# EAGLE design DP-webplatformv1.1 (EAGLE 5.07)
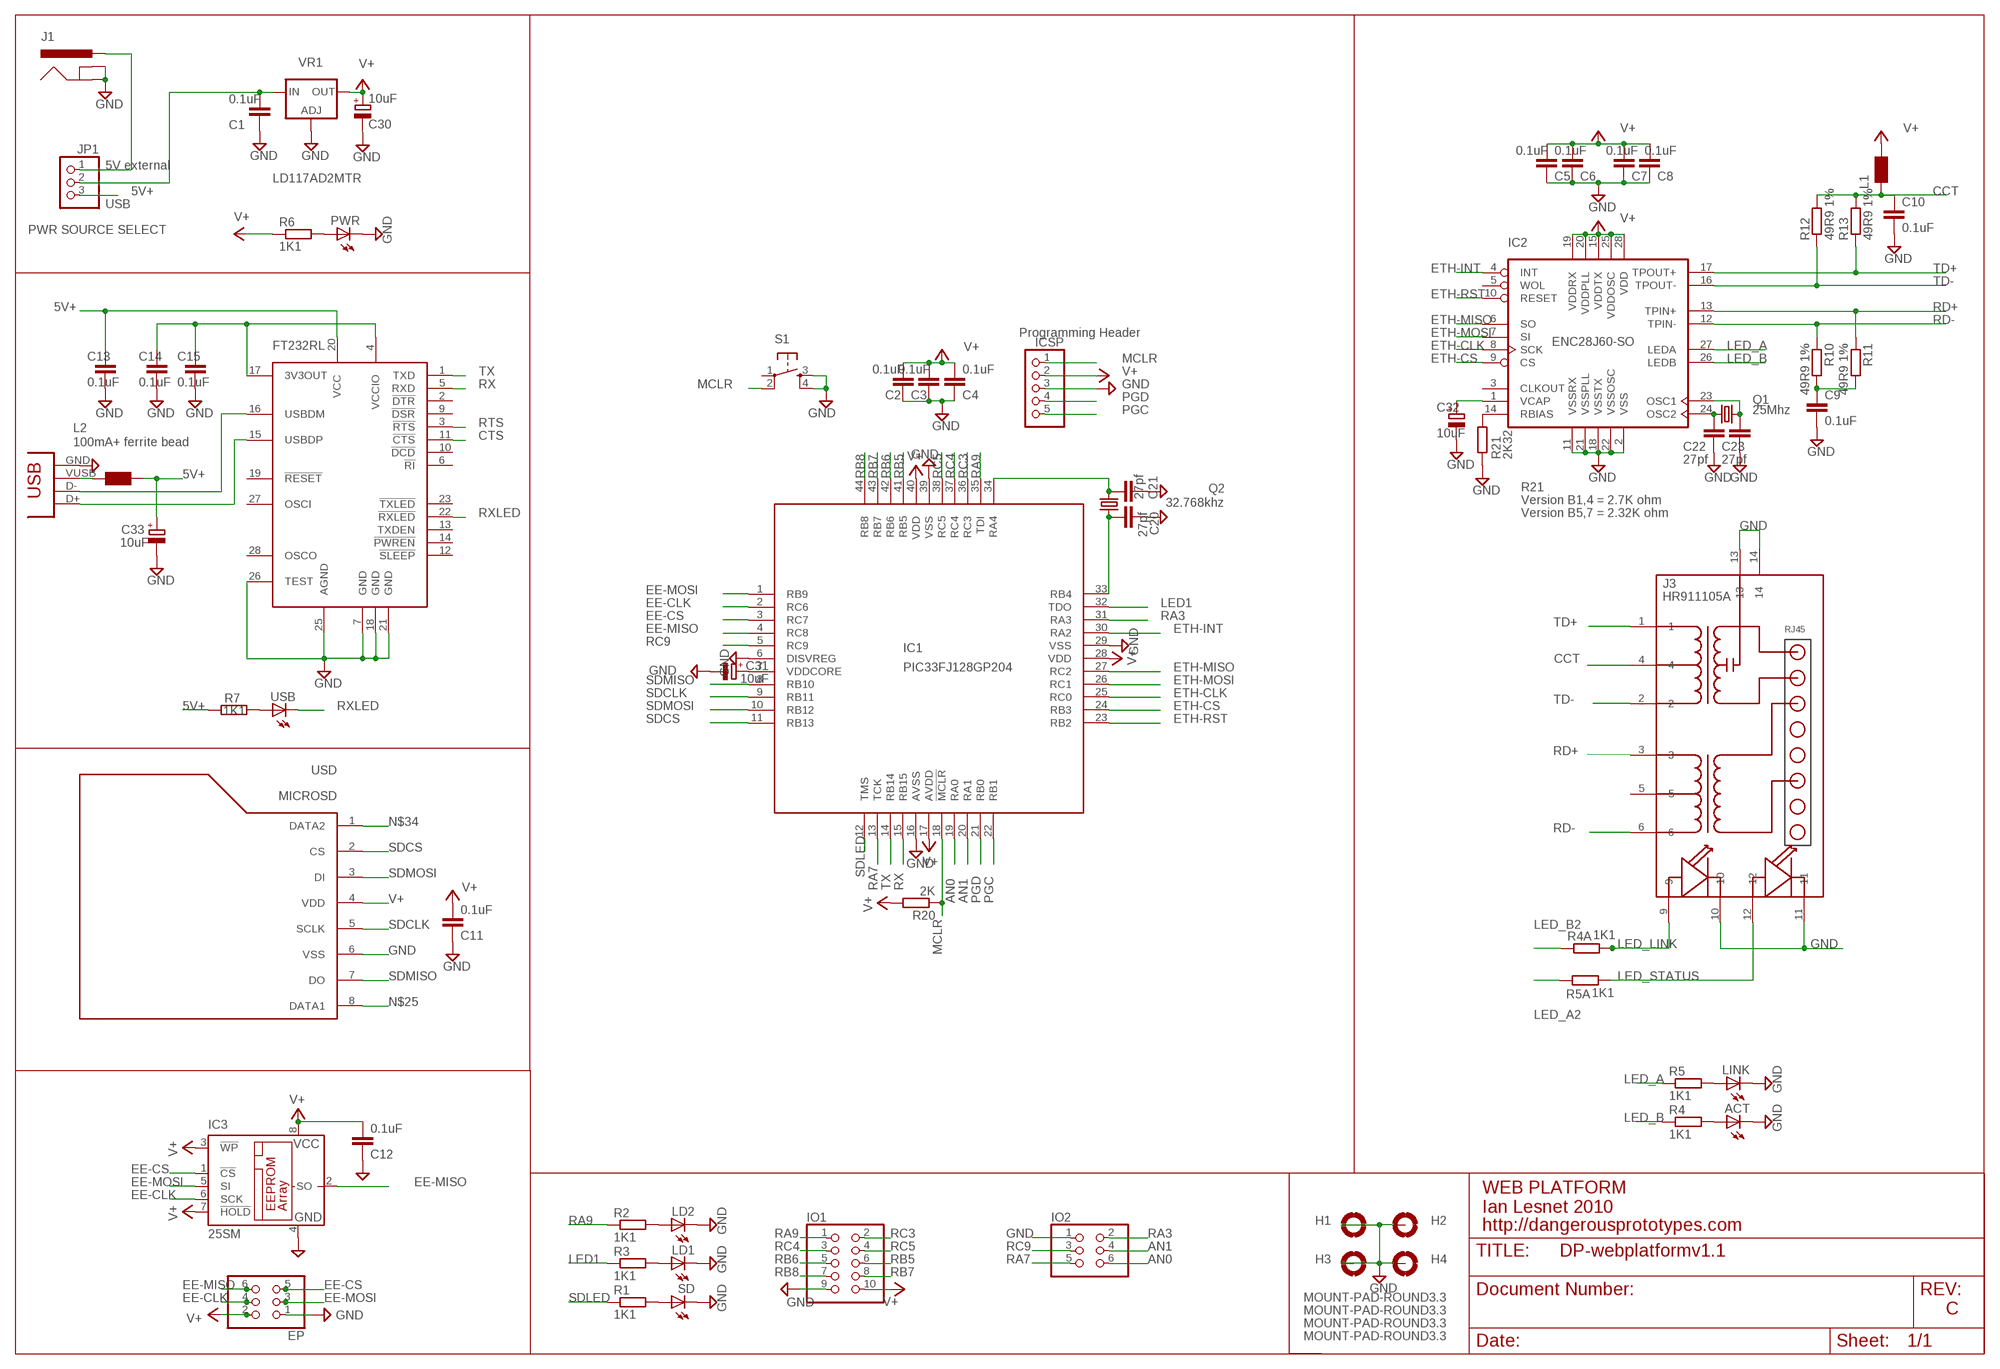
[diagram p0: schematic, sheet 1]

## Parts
ACT  LEDCHIPLED_0805  [CHIPLED_0805]
C1  0.1uF  C-EUC0805  [C0805]
C2  0.1uF  C-EUC0805  [C0805]
C3  0.1uF  C-EUC0805  [C0805]
C4  0.1uF  C-EUC0805  [C0805]
C5  0.1uF  C-EUC0805  [C0805]
C6  0.1uF  C-EUC0805  [C0805]
C7  0.1uF  C-EUC0805  [C0805]
C8  0.1uF  C-EUC0805  [C0805]
C9  0.1uF  C-EUC0805  [C0805]
C10  0.1uF  C-EUC0805  [C0805]
C11  0.1uF  C-EUC0805  [C0805]
C12  0.1uF  C-EUC0805  [C0805]
C13  0.1uF  C-EUC0805  [C0805]
C14  0.1uF  C-EUC0805  [C0805]
C15  0.1uF  C-EUC0805  [C0805]
C20  27pf  C-EUC0805  [C0805]
C21  27pf  C-EUC0805  [C0805]
C22  27pf  C-EUC0805  [C0805]
C23  27pf  C-EUC0805  [C0805]
C30  10uF  CPOL-EUSMCA  [SMC_A]
C31  10uF  CPOL-EUSMCA  [SMC_A]
C32  10uF  CPOL-EUSMCA  [SMC_A]
C33  10uF  CPOL-EUSMCA  [SMC_A]
CONN1  CONN_USB  [CONN_USB_MINI-B]
EP  PINHD-2X3  [2X03]
H1  MOUNT-PAD-ROUND3.3  [3,3-PAD]
H2  MOUNT-PAD-ROUND3.3  [3,3-PAD]
H3  MOUNT-PAD-ROUND3.3  [3,3-PAD]
H4  MOUNT-PAD-ROUND3.3  [3,3-PAD]
IC1  PIC33FJ128GP204  PIC24FJ64GA004  [TQFP44]
IC2  ENC28J60-SO  [SO28W]
IC3  25SM  [SO-08M]
IC4  FT232RL  [SSOP28]
ICSP  PINHD-1X05_2.54-S  [1X05-S]
IO1  PINHD-2X5  [2X05]
IO2  PINHD-2X3  [2X03]
J1  POWER_JACKSMD  [POWER_JACK_SMD]
J3  HR911105A  [HR911105A]
JP1  PINHD-1X03_2.54-S  [1X03-S]
L1  WE-KIL_0805  [WE-KI_0805_B]
L2  100mA+ ferrite bead  WE-KIL_0805  [WE-KI_0805_B]
LD1  LEDCHIPLED_0805  [CHIPLED_0805]
LD2  LEDCHIPLED_0805  [CHIPLED_0805]
LINK  LEDCHIPLED_0805  [CHIPLED_0805]
PWR  LEDCHIPLED_0805  [CHIPLED_0805]
Q1  25Mhz  CRYSTALHC49UP  [HC49UP]
Q2  32.768khz  CRYSTALMM20SS  [MM20SS]
R1  1K1  R-EU_R0805  [R0805]
R2  1K1  R-EU_R0805  [R0805]
R3  1K1  R-EU_R0805  [R0805]
R4  1K1  R-EU_R0805  [R0805]
R4A  1K1  R-EU_R0805  [R0805]
R5  1K1  R-EU_R0805  [R0805]
R5A  1K1  R-EU_R0805  [R0805]
R6  1K1  R-EU_R0805  [R0805]
R7  1K1  R-EU_M0805  [M0805]
R10  49R9 1%  R-EU_R0805  [R0805]
R11  49R9 1%  R-EU_R0805  [R0805]
R12  49R9 1%  R-EU_R0805  [R0805]
R13  49R9 1%  R-EU_R0805  [R0805]
R20  2K  R-EU_R0805  [R0805]
R21  2K32  R-EU_R0805  [R0805]
S1  SMD_TACT_SMALL  [TACT_SWITCH_SMALL]
SD  LEDCHIPLED_0805  [CHIPLED_0805]
USB  LEDCHIP-LED0805  [CHIP-LED0805]
USD  MICROSD  [MICROSD]
VR1  LD117AD2MTR  [D2PACK]

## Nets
5V+: C13.1 C33.+ IC4.20(VCC) JP1.3 L2.1 R7.2
AN0: IC1.19(RA0) IO2.6
AN1: IC1.20(RA1) IO2.4
BUS_PWR: CONN1.VUSB L2.2
CCT: C10.1 J3.4 L1.2 R12.2 R13.2
CTS: IC4.11(!CTS)
EE-CLK: EP.4 IC1.2(RC6) IC3.6(SCK)
EE-CS: EP.5 IC1.3(RC7) IC3.1(!CS)
EE-MISO: EP.6 IC1.4(RC8) IC3.2(SO)
EE-MOSI: EP.3 IC1.1(RB9) IC3.5(SI)
ETH-CLK: IC1.25(RC0) IC2.8(SCK)
ETH-CS: IC1.24(RB3) IC2.9(CS)
ETH-INT: IC1.30(RA2) IC2.4(INT)
ETH-MISO: IC1.27(RC2) IC2.6(SO)
ETH-MOSI: IC1.26(RC1) IC2.7(SI)
ETH-RST: IC1.23(RB2) IC2.10(RESET)
GND: ACT.C C1.2 C2.2 C3.2 C4.2 C5.2 C6.2 C7.2 C8.2 C9.2 C10.2 C11.2 C12.2 C13.2 C14.2 C15.2 C20.2 C21.2 C22.2 C23.2 C30.- C31.- C32.- C33.- CONN1.GND EP.1 H1.B3,3(MOUNT) H2.B3,3(MOUNT) H3.B3,3(MOUNT) H4.B3,3(MOUNT) IC1.6(DISVREG) IC1.16(AVSS) IC1.29(VSS) IC1.39(VSS) IC2.2(VSS) IC2.11(VSSRX) IC2.18(VSSTX) IC2.21(VSSPLL) IC2.22(VSSOSC) IC3.4(GND) IC4.7(GND) IC4.18(GND) IC4.21(GND) IC4.25(AGND) IC4.26(TEST) ICSP.3 IO1.9 IO2.1 J1.GND(GNDBREAK) J1.P$4(GND) J3.10 J3.11 J3.13 J3.14 LD1.C LD2.C LINK.C PWR.C R21.1 S1.3 S1.4 SD.C USD.6(VSS) VR1.1(ADJ)
LED1: IC1.32(TDO) R3.1
LED_A: IC2.27(LEDA) R5.1
LED_A2: R5A.1
LED_B: IC2.26(LEDB) R4.1
LED_B2: R4A.1
LED_LINK: J3.9 R4A.2
LED_STATUS: J3.12 R5A.2
MCLR: IC1.18(!MCLR) ICSP.1 R20.1 S1.2
N$5: C20.1 IC1.33(RB4) Q2.1
N$6: C32.+ IC2.1(VCAP)
N$7: IC2.14(RBIAS) R21.2
N$9: C22.1 IC2.24(OSC2) Q1.1
N$10: R7.1 USB.A
N$11: R1.2 SD.A
N$12: C23.1 IC2.23(OSC1) Q1.2
N$13: LD2.A R2.2
N$14: LINK.A R5.2
N$15: CONN1.D+ IC4.15(USBDP)
N$16: CONN1.D- IC4.16(USBDM)
N$17: C14.1 C15.1 IC4.4(VCCIO) IC4.17(3V3OUT)
N$18: C31.+ IC1.7(VDDCORE)
N$19: C21.1 IC1.34(RA4) Q2.4
N$20: ACT.A R4.2
N$22: C9.1 R10.2 R11.2
N$25: USD.8(DATA1)
N$28: LD1.A R3.2
N$29: PWR.A R6.2
N$34: USD.1(DATA2)
PGC: IC1.22(RB1) ICSP.5
PGD: IC1.21(RB0) ICSP.4
RA3: IC1.31(RA3) IO2.2
RA7: IC1.13(TCK) IO2.5
RA9: IC1.35(TDI) IO1.1 R2.1
RB5: IC1.41(RB5) IO1.6
RB6: IC1.42(RB6) IO1.5
RB7: IC1.43(RB7) IO1.8
RB8: IC1.44(RB8) IO1.7
RC3: IC1.36(RC3) IO1.2
RC4: IC1.37(RC4) IO1.3
RC5: IC1.38(RC5) IO1.4
RC9: IC1.5(RC9) IO2.3
RD+: IC2.13(TPIN+) J3.3 R11.1
RD-: IC2.12(TPIN-) J3.6 R10.1
RTS: IC4.3(!RTS)
RX: IC1.15(RB15) IC4.5(RXD)
RXLED: IC4.22(!RXLED) USB.C
SDCLK: IC1.9(RB11) USD.5(SCLK)
SDCS: IC1.11(RB13) USD.2(CS)
SDLED: IC1.12(TMS) R1.1
SDMISO: IC1.8(RB10) USD.7(DO)
SDMOSI: IC1.10(RB12) USD.3(DI)
TD+: IC2.17(TPOUT+) J3.1 R13.1
TD-: IC2.16(TPOUT-) J3.2 R12.1
TX: IC1.14(RB14) IC4.1(TXD)
V+: C2.1 C3.1 C4.1 C5.1 C6.1 C7.1 C8.1 C11.1 C12.1 C30.+ EP.2 IC1.17(AVDD) IC1.28(VDD) IC1.40(VDD) IC2.15(VDDTX) IC2.19(VDDRX) IC2.20(VDDPLL) IC2.25(VDDOSC) IC2.28(VDD) IC3.3(!WP) IC3.7(!HOLD) IC3.8(VCC) ICSP.2 IO1.10 L1.1 R6.1 R20.2 USD.4(VDD) VR1.2(OUT)
VBAT: C1.1 JP1.2 VR1.3(IN)
VEXT: J1.VIN0(PWR) JP1.1
Unconnected: IC2.3(CLKOUT) IC2.5(WOL) IC4.2(!DTR) IC4.6(!RI) IC4.9(!DSR) IC4.10(!DCD) IC4.12(!SLEEP) IC4.13(TXDEN) IC4.14(!PWREN) IC4.19(!RESET) IC4.23(!TXLED) IC4.27(OSCI) IC4.28(OSCO) J3.5 S1.1

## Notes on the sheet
- J1
- 5V external
- USB
- PWR SOURCE SELECT
- Programming Header
- R21
- Version B1,4 = 2.7K ohm
- Version B5,7 = 2.32K ohm
- WEB PLATFORM
- Ian Lesnet 2010
- http://dangerousprototypes.com
- C

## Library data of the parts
ACT LD1 LD2 LINK PWR SD USB = led:LED: LED
C1-C15 C20-C23 = rcl:C-EU: CAPACITOR, European symbol
C30-C33 = rcl:CPOL-EU: POLARIZED CAPACITOR, European symbol
CONN1 = dp_devices:CONN_USB: USB connector
EP IO2 = pinhead-2:PINHD-2X3: PIN HEADER
H1-H4 = holes:MOUNT-PAD-ROUND: MOUNTING PAD, round
IC1 = microchip:PIC24FJ64GA004: PIC24FJ64GA004 edit this description Auto generated by make-symbol-device-package-bsdl.ulp Rev. 25 Source: PIC24FJ64GA004.bsd
IC2 = microchip-enc28j60:ENC28J60-*: Microchip 10Mbit Eth. contoller with SPI interface
IC3 = microchip:25*: Serial EEPROM 4 K, SPI bus
IC4 = dp_devices:FT232RL: USB to serial UART interface
ICSP = pinhead-2:PINHD-1X05: PIN HEADER
IO1 = pinhead-2:PINHD-2X5: PIN HEADER
J1 = SparkFun:POWER_JACK: Power Jack This is the standard 5.5mm barrel jack for power. The PTH is the most common, proven, reliable, footprint. All others are experimental. The Slot footprint only works if the mill layer is transmitted to the PCB fab house so be warned. Spark Fun Electronics SKU : PRT-00119. Mating wall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
J3 = CONNECTER:HR911105A
JP1 = pinhead-2:PINHD-1X03: PIN HEADER
L1 L2 = wuerth-elektronik:WE-KIL: SMD Wire Wound Ceramic Inductor WE-KIL
Q1 Q2 = crystal:CRYSTAL: CRYSTAL
R1-R4 R4A R5 R5A R6 R10-R13 R20 R21 = rcl:R-EU_: RESISTOR, European symbol
R7 = resistor:R-EU_: RESISTOR, European symbol
S1 = dp_devices:SMD_TACT_SMALL
USD = Seeed:MICROSD
VR1 = v-reg:LD117A?*: Low drop fixed and adjustable positive voltage regulators 1 A Source: http://www.st.com/stonline/products/literature/ds/7194/ld1117axx.pdf

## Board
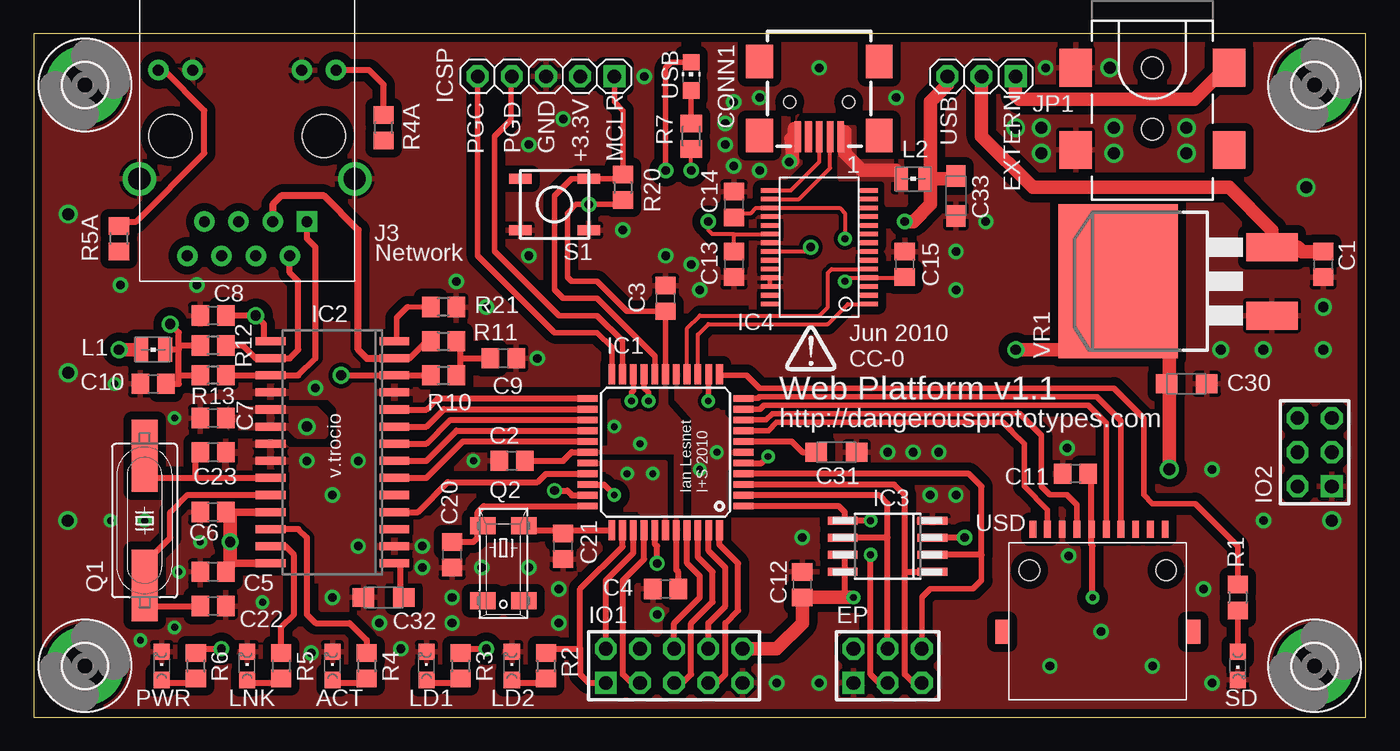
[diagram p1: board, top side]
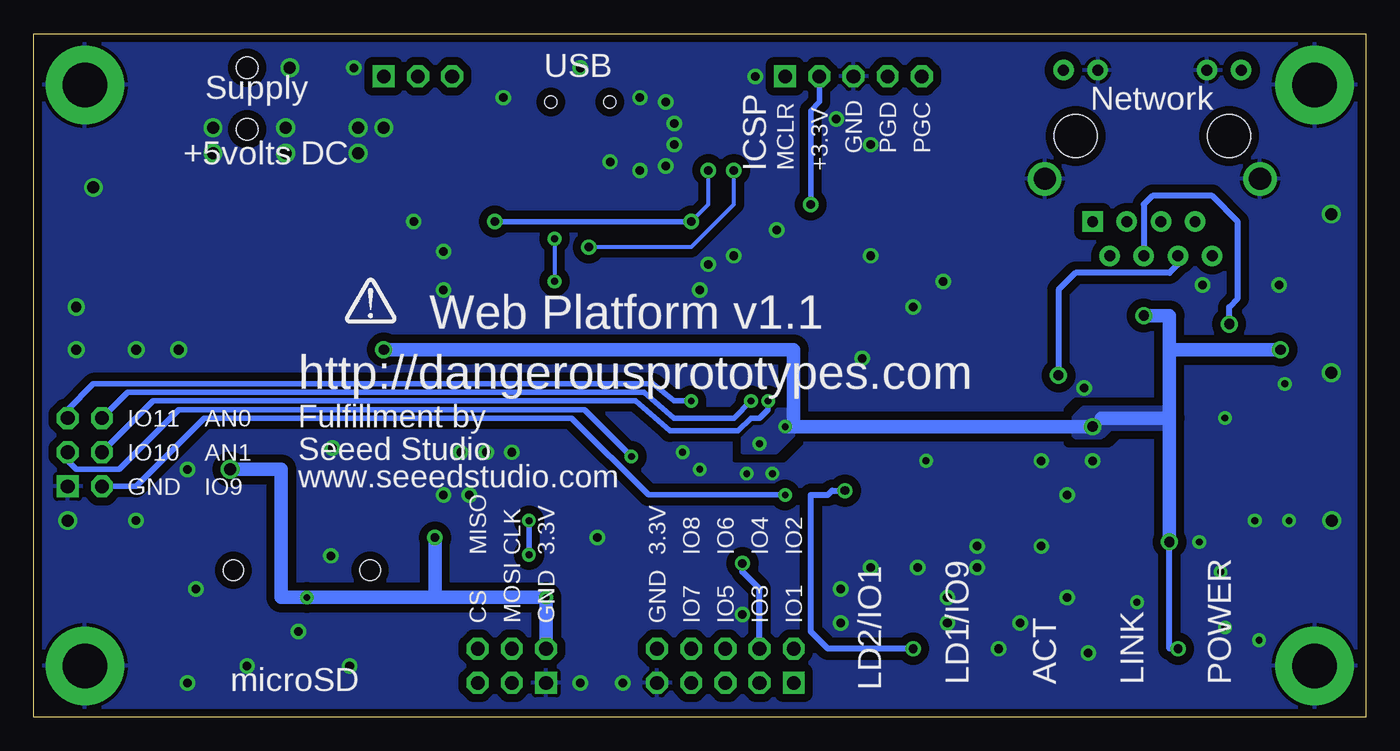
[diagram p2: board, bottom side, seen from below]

Size 99.06 x 50.8 mm. Coordinates in mm from the lower left corner, seen from the top.
Outline: 99.06,50.8 0,50.8 0,0 99.06,0 99.06,50.8
Copper layers (1*16): Top 0.035mm / dielectric 1.5mm / Bottom 0.035mm
Design rules "SparkFun": minimum track width 8mil, minimum drill 20mil, track to track 8mil, track to pad 8mil, pad to pad 8mil, via to via 8mil, smd to smd 8mil, copper to edge 10mil, drill to drill 8mil, minimum pad ring 12mil, minimum via ring 10mil, stop-mask expansion 4mil, vias tented up to drill 25mil, thermal gap 10mil

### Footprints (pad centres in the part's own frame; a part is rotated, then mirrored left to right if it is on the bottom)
CHIPLED_0805 = smd 1.2 x 1.2: A 0,-1.05; C 0,1.05
C0805 = smd 1.3 x 1.5: 1 -0.95,0; 2 0.95,0
SMC_A = smd 1.6 x 1.4: + -1.5,0; - 1.5,0
CONN_USB_MINI-B = smd 0.5 x 2.3: D+ 0,2.6; D- -0.8,2.6; GND 1.6,2.6; P4 0.8,2.6; VUSB -1.6,2.6 | smd 2 x 2.5: PC1 -4.45,2.5; PC2 4.45,2.5; PC3 4.45,-3; PC4 -4.45,-3 | hole 0.9: -2.2,0; 2.2,0
2X03 = drill 1.016 square: 1 -2.54,-1.27 | drill 1.016 octagon: 2 -2.54,1.27; 3 0,-1.27; 4 0,1.27; 5 2.54,-1.27; 6 2.54,1.27
3,3-PAD = drill 3.3 pad 5.842 round: B3,3 0,0
TQFP44 = smd 1.5 x 0.5: 1 -5.8,4; 2 -5.8,3.2; 3 -5.8,2.4; 4 -5.8,1.6; 5 -5.8,0.8; 6 -5.8,0; 7 -5.8,-0.8; 8 -5.8,-1.6; 9 -5.8,-2.4; 10 -5.8,-3.2; 11 -5.8,-4; 23 5.8,-4; 24 5.8,-3.2; 25 5.8,-2.4; 26 5.8,-1.6; 27 5.8,-0.8; 28 5.8,0; 29 5.8,0.8; 30 5.8,1.6; 31 5.8,2.4; 32 5.8,3.2; 33 5.8,4 | smd 0.5 x 1.5: 12 -4,-5.8; 13 -3.2,-5.8; 14 -2.4,-5.8; 15 -1.6,-5.8; 16 -0.8,-5.8; 17 0,-5.8; 18 0.8,-5.8; 19 1.6,-5.8; 20 2.4,-5.8; 21 3.2,-5.8; 22 4,-5.8; 34 4,5.8; 35 3.2,5.8; 36 2.4,5.8; 37 1.6,5.8; 38 0.8,5.8; 39 0,5.8; 40 -0.8,5.8; 41 -1.6,5.8; 42 -2.4,5.8; 43 -3.2,5.8; 44 -4,5.8
SO28W = smd 0.6 x 2.2: 1 -8.255,-4.6; 2 -6.985,-4.6; 3 -5.715,-4.6; 4 -4.445,-4.6; 5 -3.175,-4.6; 6 -1.905,-4.6; 7 -0.635,-4.6; 8 0.635,-4.6; 9 1.905,-4.6; 10 3.175,-4.6; 11 4.445,-4.6; 12 5.715,-4.6; 13 6.985,-4.6; 14 8.255,-4.6; 15 8.255,4.6; 16 6.985,4.6; 17 5.715,4.6; 18 4.445,4.6; 19 3.175,4.6; 20 1.905,4.6; 21 0.635,4.6; 22 -0.635,4.6; 23 -1.905,4.6; 24 -3.175,4.6; 25 -4.445,4.6; 26 -5.715,4.6; 27 -6.985,4.6; 28 -8.255,4.6
SO-08M = smd 0.6 x 2.2: 1 -1.905,-3.33; 2 -0.635,-3.33; 3 0.635,-3.33; 4 1.905,-3.33; 5 1.905,3.33; 6 0.635,3.33; 7 -0.635,3.33; 8 -1.905,3.33
SSOP28 = smd 0.348 x 1.397: 1 -4.225,-3.656; 2 -3.575,-3.656; 3 -2.925,-3.656; 4 -2.275,-3.656; 5 -1.625,-3.656; 6 -0.975,-3.656; 7 -0.325,-3.656; 8 0.325,-3.656; 9 0.975,-3.656; 10 1.625,-3.656; 11 2.275,-3.656; 12 2.925,-3.656; 13 3.575,-3.656; 14 4.225,-3.656; 15 4.225,3.656; 16 3.575,3.656; 17 2.925,3.656; 18 2.275,3.656; 19 1.625,3.656; 20 0.975,3.656; 21 0.325,3.656; 22 -0.325,3.656; 23 -0.975,3.656; 24 -1.625,3.656; 25 -2.275,3.656; 26 -2.925,3.656; 27 -3.575,3.656; 28 -4.225,3.656
1X05-S = drill 1.016 square: 1 -5.08,0 | drill 1.016 octagon: 2 -2.54,0; 3 0,0; 4 2.54,0; 5 5.08,0
2X05 = drill 1.016 square: 1 -5.08,-1.27 | drill 1.016 octagon: 2 -5.08,1.27; 3 -2.54,-1.27; 4 -2.54,1.27; 5 0,-1.27; 6 0,1.27; 7 2.54,-1.27; 8 2.54,1.27; 9 5.08,-1.27; 10 5.08,1.27
POWER_JACK_SMD = smd 2.8 x 2.4: GND 0,-5.7; P$4 6.1,-5.7; VIN0 0,5.7; VIN1 6.1,5.7 | hole 1.6: 0,0; 4.572,0
HR911105A = drill 0.813 pad 1.524 square: 1 4.445,-6.35 | drill 0.813 pad 1.524 round: 2 3.175,-8.89; 3 1.905,-6.35; 4 0.635,-8.89; 5 -0.635,-6.35; 6 -1.905,-8.89; 7 -3.175,-6.35; 8 -4.445,-8.89; 9 6.604,4.902; 10 4.064,4.902; 11 -4.064,4.902; 12 -6.604,4.902 | drill 1.651 pad 2.159 round: 13 8.001,-3.175; 14 -8.001,-3.175 | hole 3.2: 5.715,0; -5.715,0
1X03-S = drill 1.016 square: 1 -2.54,0 | drill 1.016 octagon: 2 0,0; 3 2.54,0
WE-KI_0805_B = smd 1.02 x 1.78: 1 -0.89,0; 2 0.89,0
HC49UP = smd 5.334 x 1.93: 1 -4.826,0; 2 4.826,0
MM20SS = smd 1.27 x 1.88: 1 -2.794,-1.524; 2 2.794,-1.524; 3 2.794,1.524; 4 -2.794,1.524
R0805 = smd 1.3 x 1.5: 1 -0.95,0; 2 0.95,0
M0805 = smd 1.3 x 1.6: 1 -0.95,0; 2 0.95,0
TACT_SWITCH_SMALL = smd 1.651 x 0.762: 1 -2.54,1.905; 2 2.54,1.905; 3 -2.54,-1.905; 4 2.54,-1.905
CHIP-LED0805 = smd 1.2 x 1.2: A 0,-1.05; C 0,1.05
MICROSD = smd 1.27 x 0.508: 1 0,-7.645; 2 0,-6.553; 3 0,-5.461; 4 0,-4.369; 5 0,-3.277; 6 0,-2.184; 7 0,-1.092; 8 0,0; 9 0,-8.738; 10 0,-9.83 | smd 1.778 x 1.016: RSV1 -7.62,2.286; RSV2 -7.62,-11.938 | hole 1.524: -3.048,-9.906; -3.048,0.254
D2PACK = smd 2.083 x 3.81: 1 -2.54,-8.89; 3 2.54,-8.89 | smd 11.43 x 8.89: 2 0,2.54

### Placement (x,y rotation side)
ACT  22.22,3.81 0 top
C1  95.89,33.66 270 top
C2  35.56,19.05 180 top
C3  46.99,31.11 90 top
C4  46.99,9.53 180 top
C5  13.34,10.79 180 top
C6  13.34,15.24 180 top
C7  13.34,22.23 180 top
C8  13.34,29.84 180 top
C9  34.92,26.67 0 top
C10  8.89,24.77 180 top
C11  77.47,18.1 180 top
C12  57.15,9.84 90 top
C13  52.07,33.66 270 top
C14  52.07,38.1 90 top
C15  64.77,33.66 90 top
C20  31.11,12.06 270 top
C21  39.37,12.7 270 top
C22  13.34,8.26 0 top
C23  13.34,19.68 0 top
C30  85.73,24.77 0 top
C31  59.69,19.68 0 top
C32  26.04,8.89 180 top
C33  68.58,38.73 270 top
CONN1  58.42,45.72 180 top
EP  63.5,3.81 0 top
H1  3.81,46.99 0 top
H2  95.25,46.99 0 top
H3  95.25,3.81 0 top
H4  3.81,3.81 0 top
IC1  46.99,19.68 180 top
IC2  22.22,19.68 90 top
IC3  63.5,12.7 90 top
IC4  58.42,34.92 90 top
ICSP  38.1,47.62 180 top
IO1  47.62,3.81 0 top
IO2  95.25,19.68 90 top
J1  83.19,48.26 270 top
J3  15.88,43.18 0 top
JP1  70.48,47.62 180 top
L1  8.89,27.3 0 top
L2  65.41,40.01 180 top
LD1  29.21,3.81 0 top
LD2  35.56,3.81 0 top
LINK  15.88,3.81 0 top
PWR  9.53,3.81 0 top
Q1  8.26,14.61 90 top
Q2  34.92,11.43 270 top
R1  89.53,8.89 270 top
R2  38.1,3.81 270 top
R3  31.75,3.81 270 top
R4  24.76,3.81 270 top
R4A  26.04,43.81 90 top
R5  18.41,3.81 270 top
R5A  6.35,35.56 90 top
R6  12.07,3.81 270 top
R7  48.9,43.18 270 top
R10  30.48,25.4 0 top
R11  30.48,27.94 0 top
R12  13.34,27.62 180 top
R13  13.34,25.4 180 top
R20  43.82,39.37 270 top
R21  30.48,30.48 180 top
S1  38.73,38.1 0 top
SD  89.53,3.81 180 top
U$1  [DP-LOGO]  55.88,25.72 0 top
U$2  [DP-LOGO-BOTTOM]  72.09,29.26 0 top
USB  48.9,47.62 0 top
USD  74.3,13.97 90 top
VR1  83.19,32.38 90 top

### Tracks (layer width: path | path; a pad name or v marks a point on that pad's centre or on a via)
5V+  (via drill 0.64)
  Top 0.305: v48.9,40.64 R7.2 | 52.07,35.9 50.46,35.9 50.16,36.2 v50.16,36.83 | 52.07,35.9 IC4.20 | C13.1 52.07,35.9
  Top 1.016: C33.+ 68.58,40.01 66.67,40.01 | 66.67,40.01 L2.1 66.67,40.38 66.67,45.72 67.95,46.99 JP1.3 | 66.67,40.01 66.67,38.1 65.41,36.83 v64.77,36.83
  Bottom 0.305: v48.9,40.64 48.9,38.1 v50.16,36.83
  Bottom 0.406: v50.16,36.83 v64.77,36.83
AN0  (via drill 0.51)
  Top 0.406: IC1.19 45.39,24.46 45.72,24.13 v45.72,23.5
  Bottom 0.406: v45.72,23.5 46.99,22.23 51.44,22.23 53.66,24.13 92.08,24.13 IO2.6
AN1  (via drill 0.51)
  Top 0.406: IC1.20 44.59,24.27 44.45,24.13 v44.45,23.5
  Bottom 0.406: 44.45,23.81 v44.45,23.5 44.45,22.86 45.09,22.23 45.72,22.23 46.67,21.27 51.75,21.27 54.29,23.5 90.17,23.5 IO2.4
BUS_PWR
  Top 1.016: 60.33,43.5 60.33,41.91 61.59,40.64 64.14,40.64
  pour Top: 60.01,43.81 60.96,43.81 60.96,41.27 64.77,41.27 64.77,38.1 63.5,38.1 63.5,39.69 63.18,40.01 60.01,40.01
CCT  (via drill 0.76)
  Top 0.457: 10.79,25.4 R13.2 | 10.79,25.4 10.79,27.3 | 10.79,27.3 10.79,27.62 | 10.79,27.62 10.79,28.57 v10.16,29.21 | 10.79,27.62 R12.2 | 10.79,27.3 L1.2 | C10.1 10.79,24.77 10.79,25.4
  Bottom 0.457: J3.4 16.51,38.1 15.88,38.73 11.43,38.73 9.53,36.83 9.53,31.11 10.16,30.48 v10.16,29.21
EE-CLK
  Top 0.457: EP.4 63.5,13.34 | 63.5,13.34 IC3.6 | IC1.2 62.89,16.48 63.5,15.88 63.5,13.34
EE-CS
  Top 0.457: 64.77,10.79 IC3.1 | 64.77,10.79 64.77,3.17 65.41,2.54 EP.5 | IC1.3 64,17.29 64.77,16.51 64.77,10.79
EE-MISO
  Top 0.406: EP.6 66.04,8.89 66.67,9.53 69.85,9.53 70.48,10.16 70.48,12.06
  Top 0.457: IC3.2 70.48,12.06 70.48,17.14 69.55,18.09 IC1.4
EE-MOSI  (via drill 0.51)
  Top 0.457: v62.23,14.61 IC3.5 60.33,14.76 60.33,15.24 59.88,15.69 IC1.1 | v62.23,12.06 62.23,3.17 62.87,2.54 EP.3
  Bottom 0.406: v62.23,12.06 v62.23,14.61
ETH-CLK
  Top 0.457: IC1.25 30.97,22.09 29.21,20.32 IC2.8
ETH-CS
  Top 0.457: IC1.24 30.5,22.89 29.21,21.59 IC2.9
ETH-INT
  Top 0.457: IC1.30 38.09,18.09 37.47,17.46 30.8,17.46 28.57,15.24 IC2.4
ETH-MISO
  Top 0.457: IC1.27 31.91,20.48 29.21,17.78 IC2.6
ETH-MOSI
  Top 0.406: IC2.7 27.3,19.05
  Top 0.457: IC1.26 31.45,21.29 29.21,19.05 27.3,19.05
ETH-RST
  Top 0.457: IC1.23 30.04,23.68 29.21,22.86 IC2.10
GND  (via drill 0.51, 0.64, 0.76, 0.89)
  Top 0.305: C13.2 52.07,32.38 | IC4.26 IC4.25
  Top 0.406: v56.2,41.27 56.03,43.08 56.24,43.28
  Top 0.457: CONN1.GND 56.58,43.12 56.52,43.18
  Top 0.813: v56.2,41.27 56.52,41.27 56.52,43.18 56.52,43.81
  other vias: 74.93,41.91 74.93,43.81 12.14,32.11 20.95,24.45 20.32,19.05 24.13,19.05 10.48,22.23 12.38,13.02 17.02,8.53 6.45,32.11 46.36,7.62 76.84,20 87.63,18.41 49.53,31.75 7.94,5.71 75.56,3.81 83.19,3.81 87,9.53 79.38,6.35 68.58,34.61 73.03,43.81 80.01,48.26 85.73,41.91 96.52,14.61 80.33,41.91 80.33,43.81 85.73,43.81 94.62,39.37 76.96,11.99 57.15,13.34 66.67,16.51 68.58,16.51 65.41,19.68 63.5,19.68 37.47,26.67 31.43,32.38 33.66,30.48 32.7,19.05 28.89,11.11 28.89,12.7 33.34,11.11 39.05,9.53 36.83,11.11 31.11,8.89 39.05,6.99 27.3,5.08 20.64,4.76 8.26,14.61 70.8,36.83 75.25,48.26 68.58,31.75 53.98,46.04 58.42,48.26 64.14,46.04 43.82,36.2 36.83,34.29 67.31,19.68 87.63,2.54 88.27,27.3 95.89,27.3 91.44,14.61 91.44,27.3 95.89,30.48 46.99,34.29 48.9,33.66 39.37,44.45 10.79,10.79 31.11,6.99 22.22,16.51 24.13,12.7 22.22,8.89 25.72,6.99 10.48,6.67 5.71,14.61 6.03,24.77 45.4,47.62 2.57,37.39 2.57,25.6 2.54,14.61 52.07,45.72 51.44,42.55 44.13,18.1 49.53,18.41 50.8,19.68 46.04,18.1 52.07,40.96 53.98,40.64 51.44,44.13 36.83,42.55 58.42,2.54 55.25,2.54
  pour Top (isolate 0.61, rank 2): 99.06,0 0,0 0,50.8 99.06,50.8
  pour Bottom (isolate 0.61, rank 2): 99.06,0 0,0 0,50.8 99.06,50.8
  pour Top (isolate 0.305): 53.34,38.73 62.23,38.73 62.23,29.84 53.34,29.84
  pour Top (isolate 0.254): 47.78,25.4 47.78,23.65 49.05,22.23 49.05,13.97 51.44,13.97 51.44,18.41 52.71,19.68 52.71,20.95 50.8,22.86 50.8,25.4
  pour Top (isolate 0.254): 41.28,18.89 41.28,18.41 43.18,18.41 45.09,16.51 45.09,15.24 46.83,15.24 46.83,14.61 46.99,14.61 46.99,18.89
  pour Top (isolate 0.305): 13.97,29.21 29.21,29.21 29.21,10.16 13.97,10.16 13.97,19.68 15.88,19.68 16.51,20.32 18.41,20.32 19.05,19.68 22.86,19.68 22.86,23.81 13.97,23.81
LED1  (via drill 0.64)
  Top 0.406: R3.1 32.29,5.08
  Top 0.457: IC1.32 40.03,16.48 39.69,16.83 v38.73,16.83 | 32.29,5.08 v33.66,5.08
  Bottom 0.457: v38.73,16.83 39.69,16.83 40.01,16.51 41.28,16.51 41.28,6.35 40.01,5.08 v33.66,5.08
LED_A
  Top 0.457: IC2.27 18.73,12.7 19.37,12.06 19.37,7.62 18.41,6.67 R5.1
LED_B
  Top 0.457: IC2.26 19.68,13.97 20.32,13.34 20.32,7.62 20.95,6.99 23.49,6.99 24.76,5.71 R4.1
LED_LINK
  Top 0.457: J3.9 24.94,48.08 26.04,46.99 R4A.2
LED_STATUS
  Top 0.457: J3.12 9.7,48.08 12.7,45.09 12.7,41.91 7.62,36.83 6.67,36.83 R5A.2
MCLR
  Top 0.406: ICSP.1 43.18,45.72 43.82,45.09 R20.1 43.82,40.01 S1.2 40.01,40.01 38.73,38.73 38.73,31.75 39.37,31.11 41.91,31.11 46.19,26.84 IC1.18
N$5
  Top 0.457: IC1.33 33.47,15.69 33.02,15.24 33.02,14.61 | 33.02,14.61 Q2.1 | 33.02,14.61 33.02,13.34 32.7,13.02 C20.1
N$6
  Top 0.457: IC2.1 27.3,11.43 27.3,9.12 C32.+
N$7
  Top 0.406: R21.2 27.8,30.49 26.97,29.67 26.97,28.01 IC2.14
N$9
  Top 0.457: IC2.24 11.43,16.51 10.16,15.24 10.16,13.34 8.26,11.43 Q1.1 8.26,8.26 C22.1
N$10
  Top 0.406: R7.1 USB.A
N$11
  Top 0.406: SD.A R1.2
N$12
  Top 0.457: 12.07,17.78 8.26,17.78 Q1.2 | 12.07,17.78 IC2.23 | C23.1 12.07,19.05 12.07,17.78
N$13
  Top 0.457: R2.2 38.1,2.54 35.78,2.54 LD2.A
N$14
  Top 0.457: R5.2 18.41,2.54 16.09,2.54 LINK.A
N$15
  Top 0.305: IC4.15 56.3,39.15 58.42,41.27 CONN1.D+
N$16
  Top 0.305: IC4.16 56.91,38.5 59.22,40.8 CONN1.D-
N$17  (via drill 0.51)
  Top 0.305: v60.33,35.56 60.33,37.47 59.94,37.85 IC4.17 53.73,37.85 53.34,37.47 52.39,37.47 C14.1 | v60.33,32.38 60.59,32.65 IC4.4 64.72,32.65 C15.1
  Bottom 0.305: v60.33,35.56 v60.33,32.38
N$18
  Top 0.457: IC1.7 56.35,20.48 57.15,19.68 C31.+
N$19
  Top 0.406: 39.09,13.41 C21.1 | Q2.4 36.66,14.11
  Top 0.457: 39.37,13.88 36.79,13.88 Q2.4 | 39.37,13.88 IC1.34 | 39.09,13.41 39.09,13.61 39.37,13.88
N$20
  Top 0.457: R4.2 24.76,2.54 22.45,2.54 ACT.A
N$22
  Top 0.457: R10.2 31.75,25.4 31.75,26.67 | R11.2 31.75,27.94 31.75,26.67 | 31.75,26.67 C9.1
N$28
  Top 0.457: R3.2 31.75,2.54 29.43,2.54 LD1.A
N$29
  Top 0.457: R6.2 12.07,2.54 9.74,2.54 PWR.A
PGC
  Top 0.406: ICSP.5 33.02,34.29 38.73,28.57 41.91,28.57 42.99,27.5 IC1.22
PGD
  Top 0.406: ICSP.4 35.51,47.55 35.51,44.4 34.29,43.18 34.29,34.61 39.05,29.84 41.91,29.84 43.79,27.96 IC1.21
RA3  (via drill 0.51)
  Top 0.457: IC1.31 42.41,17.29 v43.18,16.51
  Bottom 0.406: v43.18,16.51 53.34,16.51 59.05,22.23 86.36,22.23 91.44,17.14 IO2.2
RA7  (via drill 0.51)
  Top 0.406: IC1.13 50.19,24.16 50.16,24.13 v50.16,23.5
  Bottom 0.406: v50.16,23.5 51.44,23.5 53.02,24.77 94.62,24.77 96.52,22.86 IO2.5
RA9
  Top 0.457: IC1.35 43.79,12.68 40.64,9.53 40.64,5.08 | 40.64,5.08 40.64,3.17 41.28,2.54 IO1.1 | R2.1 38.1,5.08 40.64,5.08
RB5
  Top 0.457: IC1.41 48.59,11.42 49.53,10.48 49.53,8.89 47.62,6.99 IO1.6
RB6
  Top 0.457: IC1.42 49.39,11.89 50.48,10.79 50.48,8.57 48.9,6.99 48.9,3.17 48.26,2.54 IO1.5
RB7
  Top 0.457: IC1.43 50.19,12.36 51.44,11.11 51.44,8.26 50.16,6.99 IO1.8
RB8
  Top 0.457: IC1.44 50.99,12.83 52.39,11.43 52.39,7.94 51.44,6.99 51.44,3.17 50.8,2.54 IO1.7
RC3
  Top 0.457: IC1.36 44.59,12.21 42.55,10.16 IO1.2
RC4
  Top 0.457: IC1.37 45.39,11.73 43.82,10.16 43.82,3.17 44.45,2.54 IO1.3
RC5  (via drill 0.64)
  Top 0.457: IC1.38 46.19,12.87 46.36,12.7 v46.36,11.43
  Bottom 0.457: v46.36,11.43 46.36,10.79 45.09,9.53 IO1.4
RC9  (via drill 0.51)
  Top 0.457: IC1.5 54.13,18.89 v54.61,19.37
  Bottom 0.406: IO2.3 96.52,19.05 95.89,18.41 92.71,18.41 88.27,22.86 58.1,22.86 v54.61,19.37
RD+
  Top 0.457: IC2.13 27.94,26.67 29.21,27.94 R11.1
  Top 0.508: IC2.13 24.76,26.67 24.13,27.3 24.13,36.2 21.59,38.73 18.41,38.73 17.78,38.1 J3.3
RD-  (via drill 0.76)
  Top 0.457: R10.1 IC2.12 v22.86,25.4
  Bottom 0.457: J3.6 13.97,33.66 14.61,33.02 21.59,33.02 22.86,31.75 v22.86,25.4
RX
  Top 0.305: IC4.5 59.34,33.3 59.05,33.02 59.05,30.48 58.42,29.84 49.53,29.84 48.59,28.91 IC1.15
RXLED  (via drill 0.64)
  Top 0.305: IC4.22 57.46,34.6 v57.79,34.92
  Top 0.406: USB.C 47.41,48.67 46.99,48.26 v46.99,40.64
  Bottom 0.305: v57.79,34.92 50.16,34.92 46.99,38.1 v46.99,40.64
SDCLK
  Top 0.406: USD.5 77.57,15.77 76.84,16.51 75.56,16.51 74.93,17.14 74.93,20.95 73.34,22.54 54.93,22.54 54.47,22.09 IC1.9
SDCS
  Top 0.406: USD.2 80.85,22.02 79.06,23.81 53.98,23.81 53.85,23.68 IC1.11
SDLED
  Top 0.406: IC1.12 51.03,25.48 | R1.1 89.53,12.7 86.36,15.88 83.19,15.88 82.55,16.51 82.55,22.23 80.33,24.45 53.98,24.45 53.02,25.4 51.12,25.4
  Top 0.457: 51.03,25.48 51.12,25.4
SDMISO
  Top 0.406: USD.7 75.39,15.42 73.66,17.14 73.66,20.32 72.87,21.11 72.7,21.29 72.07,21.91 55.25,21.91 54.62,21.29 IC1.8
SDMOSI
  Top 0.406: USD.3 79.76,21.84 78.42,23.18 54.29,23.18 54,22.89 IC1.10
TD+
  Top 0.457: J3.1 20.32,35.56 20.95,34.92 20.95,26.67 19.68,25.4 IC2.17 R13.1
TD-
  Top 0.457: J3.2 19.05,33.02 19.68,32.38 19.68,27.3 19.05,26.67 IC2.16 16.51,26.67 15.56,27.62 R12.1
TX
  Top 0.305: IC4.1 60.55,30.7 59.05,29.21 50.16,29.21 49.39,28.43 IC1.14
V+  (via drill 0.51, 0.64, 0.76, 0.89)
  Top 0.406: C6.1 14.58,15.14 | 17.12,27.84 IC2.15 | 14.26,29.93 C8.1 14.26,29.88 14.2,29.93 | 14.58,30.38 14.58,30.31 | R20.2 43.82,38.1 v41.28,38.1 40.32,38.1 39.69,37.47 39.69,32.7 40.01,32.38 41.91,32.38 44.13,30.16 C3.1 IC1.17
  Top 0.457: C11.1 78.66,17.85 USD.4 78.66,12.78 78.74,12.7 v78.74,8.89 | v69.22,13.34 IC3.3 | IC3.7 60.33,12.06 60.33,10.95 IC3.8 60.33,10.79 60.33,8.89 | IC1.40 47.79,10.95 47.94,10.79 47.94,10.16 C4.1 | IC1.28 40.01,19.68 39.37,19.05 C2.1 | 17.12,27.84 17.12,29.23 v16.51,29.84 C8.1 14.36,30.16 14.58,30.38 | R6.1 12.07,5.08 v13.97,5.08
  Top 0.559: 14.61,15.24 C6.1 14.61,14.92 | 14.61,15.24 IC2.25 | 14.58,15.14 14.58,15.21 14.61,15.24 | C5.1 14.61,11.12 14.61,11.43 IC2.28
  Top 0.61: 14.26,29.93 14.08,30.11
  Top 1.016: v60.96,8.89 60.33,8.89 C12.1 57.15,6.99 55.25,5.08 IO1.10 | v6.35,27.3 L1.1 | 14.61,14.92 v14.61,13.02 14.61,11.43 | v73.03,27.3 80.01,27.3 | 80.01,27.3 VR1.2 | 84.45,24.77 84.45,27.3 80.01,27.3 | 84.45,24.77 v84.45,18.41 | 84.45,24.77 C30.+
  Bottom 0.406: ICSP.2 40.64,45.72 41.28,45.09 v41.28,38.1
  Bottom 0.457: v13.97,5.08 14.61,5.08 v14.61,13.02
  Bottom 1.016: v84.45,18.41 80.64,18.41 80.64,8.89 v78.74,8.89 69.22,8.89 | 69.22,8.89 v69.22,13.34 | 69.22,8.89 v60.96,8.89 EP.2 | 14.61,27.3 v6.35,27.3 | v16.51,29.84 14.61,29.84 14.61,27.3 | v14.61,13.02 14.61,22.23 | 14.61,22.23 14.61,27.3 | 14.61,22.23 19.68,22.23 | v20.32,21.59 42.55,21.59 | 42.55,21.59 v43.18,21.59 | 42.55,21.59 42.55,27.3 v73.03,27.3
  other vias: 45.09,20.32
  pour Top (isolate 0.254): 42.86,23.5 46.67,23.5 46.67,25.4 46.99,25.4 46.99,23.18 48.1,21.91 48.1,13.97 47.78,13.97 47.78,19.68 41.28,19.68 41.28,20 42.86,20
  pour Top (isolate 0.305): 14.61,22.86 20.95,22.86 21.59,22.23 21.59,20.95 19.68,20.95 19.05,21.59 14.61,21.59
  pour Bottom (isolate 0.305): 42.55,20.95 42.55,22.86 46.36,22.86 46.36,19.68 43.82,19.68
  pour Bottom (isolate 0.305): 14.61,22.86 20.95,22.86 21.59,22.23 21.59,20.95 19.68,20.95 19.05,21.59 14.61,21.59
VBAT
  Top 1.016: JP1.2 70.48,43.18 74.3,39.37 88.9,39.37 92.08,36.2 VR1.3 93.98,34.92 94.3,34.6 C1.1
VEXT
  Top 1.016: JP1.1 73,46.23 73.3,45.92 86.31,45.92 89.05,48.67 J1.VIN0

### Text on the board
tNames: USB | USB | EXTERN | PGC | PGD | GND | +3.3V | MCLR | Network | Jun 2010 | CC-0 | Web Platform v1.1 | http://dangerousprototypes.com | v.trocio | Ian Lesnet | I+S 2010 | PWR | LNK | ACT | LD1 | LD2 | SD
bNames: USB | ICSP | Supply | Network | PGC | PGD | GND | +3.3V | MCLR | +5volts DC | Web Platform v1.1 | http://dangerousprototypes.com | Fulfillment by | AN0 | IO11 | Seeed Studio | AN1 | IO10 | www.seeedstudio.com | IO9 | GND | IO2 | IO4 | IO6 | IO8 | 3.3V | 3.3V | CLK | MISO | IO1 | IO3 | IO5 | IO7 | GND | GND | MOSI | CS | POWER | LINK | ACT | LD1/IO9 | LD2/IO1 | microSD
tValues: RA0 | RA1 | GND | V+ | GND | RB15 | MCLR | V+ | GND | PGD3 | PGC3
Reference: ICSP | Supply | Network | +5volts DC | USB | PGC | PGD | GND | MCLR | +3.3V | WEB PLATFORM | CC-0 | Ian Lesnet 2010 | http://dangerousprototypes.com | Indicator LEDs | microSD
